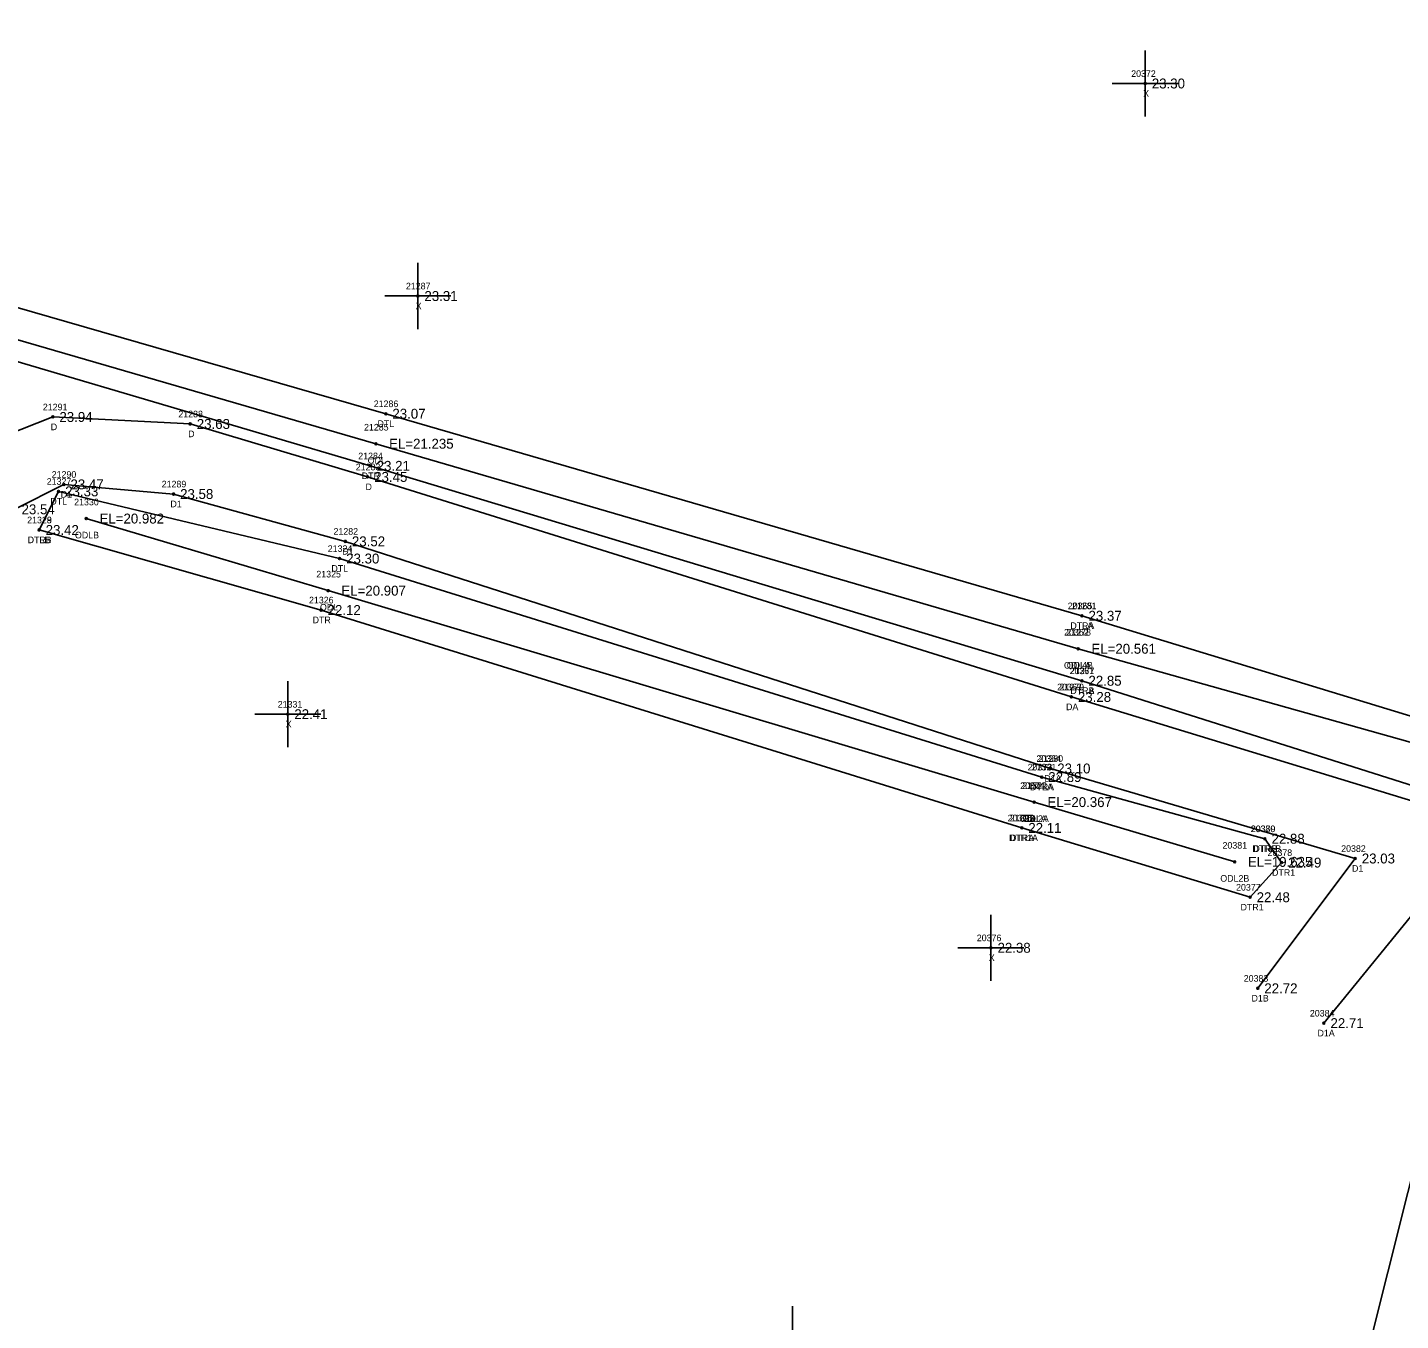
# Model space of a CAD drawing. Extents: x 2655177 to 2656219, y 761780 to 764748.
# Drawn here: x 2655601.7 to 2655809.5, y 763790 to 763985.6 of the extents above; entities that cross this region are included whole.
import ezdxf

# ---------------------------------------------------------------- set-up
doc = ezdxf.new("R2010")
doc.units = 0
for name, color, linetype in [('RD_EX_Driveway', 7, 'Continuous'), ('RD_EX_Driveway_txCode', 7, 'Continuous'), ('RD_EX_H2O', 7, 'Continuous'), ('RD_EX_H2O_txCode', 7, 'Continuous'), ('RD_EX_Misc', 7, 'Continuous'), ('RD_EX_Misc_txCode', 7, 'Continuous'), ('RD_EX_TX_Driveway_ELEV', 7, 'Continuous'), ('RD_EX_TX_H2O_ELEV', 7, 'Continuous'), ('RD_EX_TX_Misc_ELEV', 7, 'Continuous'), ('RD_SMD_Locator', 7, 'Continuous')]:
    doc.layers.add(name, color=color, linetype=linetype)

msp = doc.modelspace()

# ---------------------------------------------------------------- linework, layer by layer
at = {"layer": 'RD_EX_Driveway'}
for points in [[(2655759.7, 763884.33), (2655653.19, 763917.62), (2655626.34, 763925.63), (2655605.55, 763926.69), (2655593.12, 763921.81), (2655578.32, 763907.27), (2655560.98, 763849.55), (2655542.86, 763829.49), (2655529.97, 763828.22), (2655450.25, 763846.14)], [(2655756.57, 763873.51), (2655649.82, 763907.87), (2655623.82, 763915.03), (2655607.22, 763916.49), (2655599.82, 763912.72), (2655591.27, 763901.52), (2655575.86, 763842.69), (2655573.6, 763809.46)], [(2655759.7, 763884.33), (2655819.96, 763865.96), (2655826.61, 763863.5)], [(2655756.57, 763873.51), (2655802.66, 763859.89), (2655787.91, 763840.25)], [(2655797.92, 763834.98), (2655813.7, 763854.36), (2655825.16, 763854.34)]]:
    msp.add_lwpolyline(points, dxfattribs=at)
at = {"layer": 'RD_EX_H2O'}
for p, q in [((2655832.49, 763871.41), (2655760.74, 763891.62)), ((2655755.21, 763872.21), (2655789, 763862.88)), ((2655754.08, 763868.42), (2655784.42, 763859.38))]:
    msp.add_line(p, q, dxfattribs=at)
for points in [[(2655985.99, 764532.58), (2655990.84, 764527.53), (2655967.74, 764432.27), (2655946, 764335.4), (2655922.66, 764238.07), (2655902.06, 764145.42), (2655879.59, 764053.25), (2655859.1, 763959.14), (2655841.15, 763874.16), (2655837.57, 763865.39), (2655829.11, 763865.29), (2655761.29, 763886.78)], [(2655761.3, 763896.61), (2655655.94, 763927.18), (2655556.7, 763955.75), (2655492.71, 763974.97), (2655490.34, 763966.93)], [(2655760.74, 763891.62), (2655654.45, 763922.64), (2655555.92, 763951.2), (2655495.53, 763969.95)], [(2655761.29, 763886.78), (2655653.57, 763919.29), (2655555.16, 763948.34), (2655490.34, 763966.93)], [(2655761.3, 763896.61), (2655826.98, 763876.56), (2655847.97, 763961.11)], [(2655755.21, 763872.21), (2655648.95, 763905.27), (2655606.42, 763915.43), (2655603.47, 763909.59)], [(2655754.08, 763868.42), (2655647.22, 763900.41), (2655610.62, 763911.32)], [(2655752.19, 763864.52), (2655646.14, 763897.48), (2655603.47, 763909.59)], [(2655752.19, 763864.52), (2655786.75, 763854.03), (2655791.52, 763859.27), (2655789, 763862.88)], [(2655815.89, 763850.53), (2655812.51, 763836.78), (2655816.76, 763833.86), (2655801.46, 763772.79), (2655777.62, 763675.45), (2655757.45, 763580.99)]]:
    msp.add_lwpolyline(points, dxfattribs=at)
at = {"layer": 'RD_EX_Misc'}
for p, q in [((2655770.88, 763972.14), (2655770.88, 763982.14)), ((2655765.88, 763977.14), (2655775.88, 763977.14)), ((2655660.79, 763939.99), (2655660.79, 763949.99)), ((2655655.79, 763944.99), (2655665.79, 763944.99)), ((2655641.1, 763876.72), (2655641.1, 763886.72)), ((2655636.1, 763881.72), (2655646.1, 763881.72)), ((2655747.53, 763841.38), (2655747.53, 763851.38)), ((2655742.53, 763846.38), (2655752.53, 763846.38)), ((2655717.48, 763782.15), (2655717.48, 763792.15))]:
    msp.add_line(p, q, dxfattribs=at)
at = {"layer": 'RD_SMD_Locator'}
for centre in [(2655770.88, 763977.14), (2655660.79, 763944.99), (2655605.55, 763926.69), (2655626.34, 763925.63), (2655655.94, 763927.18), (2655654.45, 763922.64), (2655653.19, 763917.62), (2655653.57, 763919.29), (2655606.42, 763915.43), (2655607.22, 763916.49), (2655623.82, 763915.03), (2655610.62, 763911.32), (2655603.47, 763909.59), (2655603.47, 763909.59), (2655649.82, 763907.87), (2655648.95, 763905.27), (2655647.22, 763900.41), (2655646.14, 763897.48), (2655761.3, 763896.61), (2655761.3, 763896.61), (2655760.74, 763891.62), (2655760.74, 763891.62), (2655761.29, 763886.78), (2655761.29, 763886.78), (2655759.7, 763884.33), (2655759.7, 763884.33), (2655641.1, 763881.72), (2655755.21, 763872.21), (2655755.21, 763872.21), (2655756.57, 763873.51), (2655756.57, 763873.51), (2655754.08, 763868.42), (2655754.08, 763868.42), (2655752.19, 763864.52), (2655752.19, 763864.52), (2655789, 763862.88), (2655789, 763862.88), (2655784.42, 763859.38), (2655791.52, 763859.27), (2655802.66, 763859.89), (2655786.75, 763854.03), (2655747.53, 763846.38), (2655787.91, 763840.25), (2655797.92, 763834.98)]:
    msp.add_circle(centre, 0.15, dxfattribs=at)

# ---------------------------------------------------------------- texts
at = {"layer": 'RD_EX_Driveway_txCode'}
for s, p in [('21291', (2655604.04, 763927.69)), ('21288', (2655624.55, 763926.63)), ('D', (2655605.24, 763924.69)), ('D', (2655626.03, 763923.63)), ('21283', (2655651.4, 763918.62)), ('21290', (2655605.38, 763917.49)), ('D1', (2655606.75, 763914.49)), ('21289', (2655622.03, 763916.03)), ('D', (2655652.88, 763915.62)), ('D1', (2655623.35, 763913.03)), ('21282', (2655648.03, 763908.87)), ('D1', (2655649.35, 763905.87)), ('20363', (2655757.55, 763885.33)), ('21279', (2655757.9, 763885.33)), ('DA', (2655758.9, 763882.33)), ('DA', (2655758.9, 763882.33)), ('20364', (2655754.42, 763874.51)), ('21280', (2655754.73, 763874.51)), ('D1A', (2655755.6, 763871.51)), ('D1A', (2655755.6, 763871.51)), ('20382', (2655800.54, 763860.89)), ('D1', (2655802.18, 763857.89)), ('20383', (2655785.79, 763841.25)), ('D1B', (2655786.97, 763838.25)), ('20384', (2655795.8, 763835.98)), ('D1A', (2655796.96, 763832.98))]:
    msp.add_text(s, height=1, dxfattribs=at).set_placement(p)
at = {"layer": 'RD_EX_H2O_txCode'}
for s, p in [('21286', (2655654.12, 763928.18)), ('DTL', (2655654.69, 763925.18)), ('21285', (2655652.65, 763924.64)), ('21284', (2655651.78, 763920.29)), ('ODL', (2655653.2, 763919.64)), ('21327', (2655604.63, 763916.43)), ('DTR', (2655652.3, 763917.29)), ('DTL', (2655605.18, 763913.43)), ('21330', (2655608.78, 763913.32)), ('21328', (2655601.67, 763910.59)), ('21329', (2655601.67, 763910.59)), ('ODLB', (2655608.9, 763908.32)), ('DTRB', (2655601.73, 763907.59)), ('DTLB', (2655601.75, 763907.59)), ('21324', (2655647.16, 763906.27)), ('21325', (2655645.43, 763902.41)), ('DTL', (2655647.71, 763903.27)), ('21326', (2655644.32, 763898.48)), ('ODL', (2655645.98, 763897.41)), ('20365', (2655759.16, 763897.61)), ('21281', (2655759.79, 763897.61)), ('DTR', (2655644.87, 763895.48)), ('20362', (2655758.6, 763893.62)), ('21278', (2655758.95, 763893.62)), ('DTRA', (2655759.54, 763894.61)), ('DTLA', (2655759.57, 763894.61)), ('ODL4B', (2655758.58, 763888.62)), ('ODLA', (2655759.01, 763888.62)), ('20361', (2655759.43, 763887.78)), ('21277', (2655759.5, 763887.78)), ('DTRA', (2655759.54, 763884.78)), ('DTRB', (2655759.55, 763884.78)), ('20373', (2655753.09, 763873.21)), ('21321', (2655753.7, 763873.21)), ('20374', (2655751.96, 763870.42)), ('21322', (2655752.28, 763870.42)), ('DTRA', (2655753.45, 763870.21)), ('DTLA', (2655753.48, 763870.21)), ('20375', (2655750.07, 763865.52)), ('21323', (2655750.39, 763865.52)), ('ODL2A', (2655751.9, 763865.42)), ('ODLA', (2655752.34, 763865.42)), ('DTR1A', (2655750.26, 763862.52)), ('DTRA', (2655750.43, 763862.52)), ('20380', (2655786.84, 763863.88)), ('20379', (2655786.88, 763863.88)), ('20381', (2655782.58, 763861.38)), ('DTR1B', (2655787.09, 763860.88)), ('DTRB', (2655787.26, 763860.88)), ('20378', (2655789.4, 763860.27)), ('ODL2B', (2655782.25, 763856.38)), ('DTR1', (2655790.08, 763857.27)), ('20377', (2655784.63, 763855.03)), ('DTR1', (2655785.31, 763852.03))]:
    msp.add_text(s, height=1, dxfattribs=at).set_placement(p)
at = {"layer": 'RD_EX_Misc_txCode'}
for s, p in [('20372', (2655768.76, 763978.14)), ('X', (2655770.57, 763975.14)), ('21287', (2655658.99, 763945.99)), ('X', (2655660.47, 763942.99)), ('21331', (2655639.59, 763882.72)), ('X', (2655640.79, 763879.72)), ('20376', (2655745.39, 763847.38)), ('X', (2655747.21, 763844.38))]:
    msp.add_text(s, height=1, dxfattribs=at).set_placement(p)
at = {"layer": 'RD_EX_TX_Driveway_ELEV'}
for s, p in [('23.94', (2655606.55, 763925.94)), ('23.63', (2655627.34, 763924.88)), ('23.45', (2655654.19, 763916.87)), ('23.47', (2655608.22, 763915.74)), ('23.58', (2655624.82, 763914.28)), ('23.54', (2655600.82, 763911.97)), ('23.52', (2655650.82, 763907.12)), ('23.28', (2655760.7, 763883.58)), ('23.28', (2655760.7, 763883.58)), ('23.10', (2655757.57, 763872.76)), ('23.10', (2655757.57, 763872.76)), ('23.03', (2655803.66, 763859.14)), ('22.72', (2655788.91, 763839.5)), ('22.71', (2655798.92, 763834.23))]:
    msp.add_text(s, height=1.5, dxfattribs=at).set_placement(p)
at = {"layer": 'RD_EX_TX_H2O_ELEV'}
for s, p in [('23.07', (2655656.94, 763926.43)), ('EL=21.235', (2655656.45, 763921.89)), ('23.21', (2655654.57, 763918.54)), ('23.33', (2655607.42, 763914.68)), ('EL=20.982', (2655612.62, 763910.57)), ('23.42', (2655604.47, 763908.84)), ('23.42', (2655604.47, 763908.84)), ('23.30', (2655649.95, 763904.52)), ('EL=20.907', (2655649.22, 763899.66)), ('22.12', (2655647.14, 763896.73)), ('23.37', (2655762.3, 763895.86)), ('23.37', (2655762.3, 763895.86)), ('EL=20.561', (2655762.74, 763890.87)), ('EL=20.561', (2655762.74, 763890.87)), ('22.85', (2655762.29, 763886.03)), ('22.85', (2655762.29, 763886.03)), ('22.89', (2655756.21, 763871.46)), ('22.89', (2655756.21, 763871.46)), ('EL=20.367', (2655756.08, 763867.67)), ('EL=20.367', (2655756.08, 763867.67)), ('22.11', (2655753.19, 763863.77)), ('22.11', (2655753.19, 763863.77)), ('22.88', (2655790, 763862.13)), ('22.88', (2655790, 763862.13)), ('EL=19.635', (2655786.42, 763858.63)), ('22.49', (2655792.52, 763858.52)), ('22.48', (2655787.75, 763853.28))]:
    msp.add_text(s, height=1.5, dxfattribs=at).set_placement(p)
at = {"layer": 'RD_EX_TX_Misc_ELEV'}
for s, p in [('23.30', (2655771.88, 763976.39)), ('23.31', (2655661.79, 763944.24)), ('22.41', (2655642.1, 763880.97)), ('22.38', (2655748.53, 763845.63))]:
    msp.add_text(s, height=1.5, dxfattribs=at).set_placement(p)

doc.saveas('drawing.dxf')
